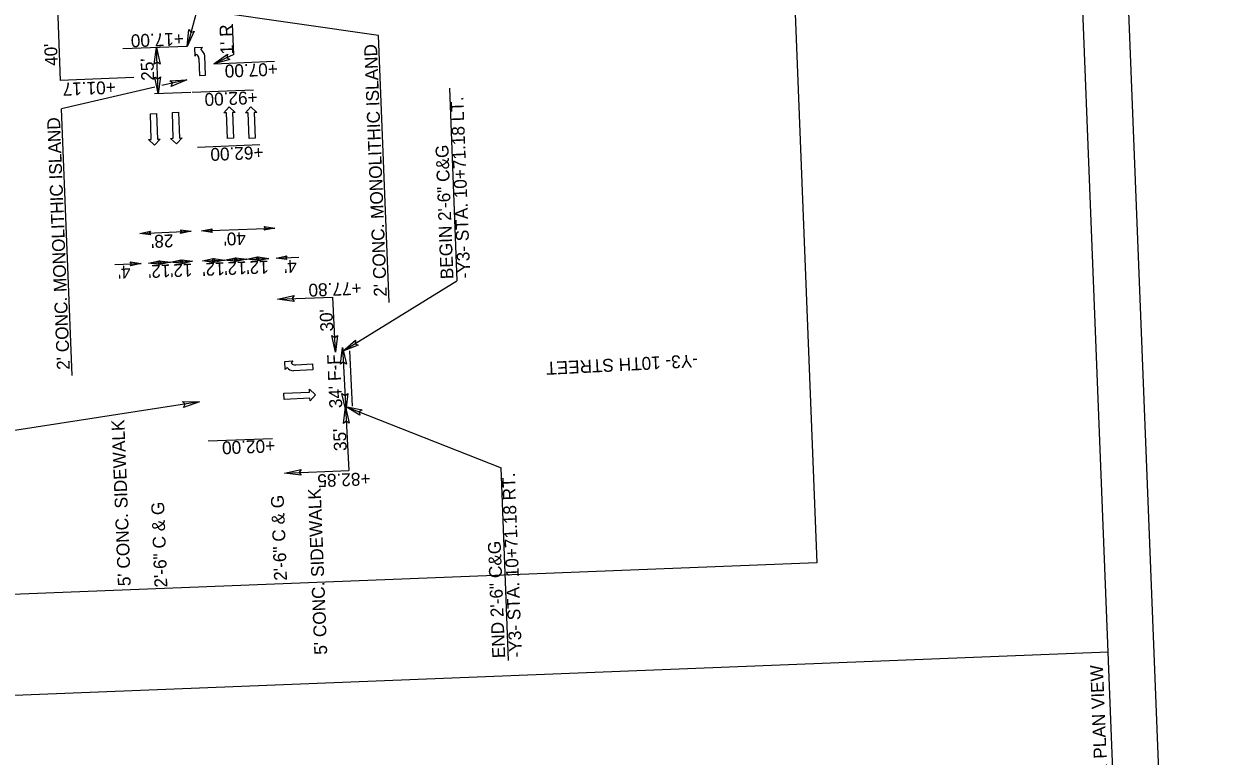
# Model space of a CAD drawing. Extents: x 1627847 to 1629013, y 761524 to 763498.
# Drawn here: x 1628362 to 1629013, y 762434 to 762832 of the extents above; entities that cross this region are included whole.
import ezdxf

# ---------------------------------------------------------------- set-up
doc = ezdxf.new("R2010")
doc.units = 0
for name, color, linetype in [('Default', 7, 'Continuous'), ('Prop Dimension', 7, 'Continuous'), ('Prop Dimension Text', 7, 'Continuous'), ('Prop DSN Text', 7, 'Continuous'), ('Prop Lane Arrow CELL', 7, 'Continuous'), ('Prop Terminator CELL', 7, 'Continuous'), ('Sheet Clip Boundary CELL', 7, 'Continuous'), ('Sheet Plan And Profile CELL', 7, 'Continuous'), ('Sheet Plot Border Outside CELL', 7, 'Continuous')]:
    doc.layers.add(name, color=color, linetype=linetype)

msp = doc.modelspace()

# ---------------------------------------------------------------- linework, layer by layer
at = {"layer": 'Prop Dimension'}
for p, q in [((1628380.25, 762841.46), (1628381.83, 762801.49)), ((1628455.98, 762838.88), (1628450.91, 762820.05)), ((1628555.02, 762825.91), (1628465.18, 762838.91)), ((1628476.2, 762815.65), (1628475.55, 762832.13)), ((1628560.75, 762680.76), (1628555.02, 762825.91)), ((1628450.91, 762820.05), (1628415.93, 762818.67)), ((1628435.17, 762794.41), (1628434.18, 762819.39)), ((1628476.2, 762815.65), (1628465.29, 762810.61)), ((1628465.29, 762810.61), (1628498.35, 762811.92)), ((1628421.8, 762803.07), (1628381.83, 762801.49)), ((1628450.62, 762801.91), (1628437, 762798.75)), ((1628433.2, 762797.87), (1628382.56, 762786.1)), ((1628433.18, 762794.34), (1628452.89, 762795.11)), ((1628453.53, 762795.14), (1628486.96, 762796.46)), ((1628593.53, 762797.3), (1628597.66, 762692.41)), ((1628388.28, 762640.95), (1628382.56, 762786.1)), ((1628456.54, 762765.23), (1628490.44, 762766.57)), ((1628425.15, 762718.31), (1628453.12, 762719.42)), ((1628458.62, 762719.63), (1628498.59, 762721.21)), ((1628441.78, 762702.6), (1628453.77, 762703.08)), ((1628459.26, 762703.29), (1628471.25, 762703.77)), ((1628471.25, 762703.77), (1628483.25, 762704.24)), ((1628483.25, 762704.24), (1628495.24, 762704.71)), ((1628499.23, 762704.87), (1628511.64, 762705.36)), ((1628411.49, 762701.41), (1628425.79, 762701.97)), ((1628429.79, 762702.13), (1628441.78, 762702.6)), ((1628535.51, 762654.11), (1628597.66, 762692.41)), ((1628500.08, 762682.48), (1628530.06, 762683.66)), ((1628531.58, 762653.7), (1628530.06, 762683.66)), ((1628535.41, 762656.11), (1628537.14, 762622.15)), ((1628457.54, 762626.57), (1628285.96, 762600.1)), ((1628537.01, 762623.94), (1628538.78, 762589.19)), ((1628537.04, 762624.15), (1628621.61, 762590.77)), ((1628462.38, 762605.34), (1628497.35, 762606.72)), ((1628503.85, 762587.81), (1628538.78, 762589.19)), ((1628625.75, 762485.94), (1628621.61, 762590.77)), ((1627902.73, 762449.14), (1628951.92, 762490.52))]:
    msp.add_line(p, q, dxfattribs=at)
at = {"layer": 'Prop Dimension Text'}
msp.add_line((1628540.86, 762624.34), (1628539.33, 762654.3), dxfattribs=at)
at = {"layer": 'Prop Lane Arrow CELL'}
for p, q in [((1628459.28, 762819.36), (1628454.89, 762819.25)), ((1628454.89, 762819.25), (1628455, 762814.75)), ((1628455, 762814.75), (1628456.01, 762815.84)), ((1628458.27, 762818.27), (1628459.28, 762819.36)), ((1628460.87, 762804.36), (1628460.49, 762814.9)), ((1628457.25, 762813.38), (1628457.58, 762804.24)), ((1628457.58, 762804.24), (1628460.87, 762804.36)), ((1628430.85, 762783.39), (1628434.15, 762783.51)), ((1628431.35, 762769.4), (1628430.85, 762783.39)), ((1628434.15, 762783.51), (1628434.65, 762769.52)), ((1628442.82, 762784.05), (1628446.12, 762784.17)), ((1628443.33, 762770.06), (1628442.82, 762784.05)), ((1628446.12, 762784.17), (1628446.62, 762770.18)), ((1628470.74, 762783.88), (1628473.72, 762787.14)), ((1628472.24, 762783.94), (1628470.74, 762783.88)), ((1628472.74, 762769.94), (1628472.24, 762783.94)), ((1628473.72, 762787.14), (1628477.03, 762784.11)), ((1628477.03, 762784.11), (1628475.53, 762784.05)), ((1628475.53, 762784.05), (1628476.04, 762770.06)), ((1628482.54, 762783.87), (1628485.53, 762787.13)), ((1628484.04, 762783.93), (1628482.54, 762783.87)), ((1628484.54, 762769.94), (1628484.04, 762783.93)), ((1628485.53, 762787.13), (1628488.84, 762784.1)), ((1628488.84, 762784.1), (1628487.34, 762784.05)), ((1628487.34, 762784.05), (1628487.84, 762770.06)), ((1628429.85, 762769.34), (1628431.35, 762769.4)), ((1628433.16, 762766.31), (1628429.85, 762769.34)), ((1628436.15, 762769.57), (1628433.16, 762766.31)), ((1628434.65, 762769.52), (1628436.15, 762769.57)), ((1628441.83, 762770.01), (1628443.33, 762770.06)), ((1628445.14, 762766.97), (1628441.83, 762770.01)), ((1628448.12, 762770.23), (1628445.14, 762766.97)), ((1628446.62, 762770.18), (1628448.12, 762770.23)), ((1628476.04, 762770.06), (1628472.74, 762769.94)), ((1628487.84, 762770.06), (1628484.54, 762769.94)), ((1628503.92, 762648.65), (1628508.41, 762648.94)), ((1628504.2, 762644.26), (1628503.92, 762648.65)), ((1628505.2, 762645.36), (1628504.2, 762644.26)), ((1628508.41, 762648.94), (1628507.42, 762647.83)), ((1628509.98, 762646.82), (1628519.11, 762647.31)), ((1628519.11, 762647.31), (1628519.29, 762644.01)), ((1628519.29, 762644.01), (1628508.75, 762643.45)), ((1628503.51, 762631.27), (1628517.5, 762631.93)), ((1628503.67, 762627.97), (1628503.51, 762631.27)), ((1628517.5, 762631.93), (1628517.43, 762633.43)), ((1628517.43, 762633.43), (1628520.72, 762630.48)), ((1628517.65, 762628.63), (1628503.67, 762627.97)), ((1628517.72, 762627.13), (1628517.65, 762628.63)), ((1628520.72, 762630.48), (1628517.72, 762627.13))]:
    msp.add_line(p, q, dxfattribs=at)
for centre, radius, start, end in [((1628453.99, 762813.28), 3.28, 2.05859, 51.71676), ((1628455.35, 762813.92), 5.25, 10.73466, 56.04636), ((1628509.27, 762648.66), 5.25, 219.07341, 264.3851), ((1628509.79, 762650.07), 3.28, 223.403, 273.06118)]:
    msp.add_arc(centre, radius, start, end, dxfattribs=at)
at = {"layer": 'Prop Terminator CELL'}
for points in [[(1628454.75, 762828.34), (1628450.91, 762820.05), (1628451.72, 762829.21), (1628452.96, 762827.68)], [(1628432.99, 762810.34), (1628434.18, 762819.39), (1628436.14, 762810.41), (1628434.5, 762811.5)], [(1628474.11, 762812.98), (1628465.29, 762810.61), (1628472.83, 762815.86), (1628472.46, 762813.93)], [(1628436.36, 762803.47), (1628435.17, 762794.41), (1628433.21, 762803.39), (1628434.86, 762802.31)], [(1628441.5, 762801.39), (1628450.62, 762801.91), (1628442.17, 762798.31), (1628442.93, 762800.13)], [(1628431.02, 762717.48), (1628425.15, 762718.31), (1628430.99, 762719.53), (1628430.28, 762718.47)], [(1628447.25, 762720.25), (1628453.12, 762719.42), (1628447.28, 762718.2), (1628447.99, 762719.26)], [(1628464.5, 762718.8), (1628458.62, 762719.63), (1628464.47, 762720.85), (1628463.75, 762719.79)], [(1628492.71, 762722.04), (1628498.59, 762721.21), (1628492.74, 762719.99), (1628493.46, 762721.06)], [(1628435.67, 762701.35), (1628429.79, 762702.13), (1628435.62, 762703.4), (1628434.92, 762702.33)], [(1628435.89, 762703.38), (1628441.78, 762702.6), (1628435.94, 762701.33), (1628436.65, 762702.4)], [(1628447.66, 762701.83), (1628441.78, 762702.6), (1628447.61, 762703.87), (1628446.91, 762702.81)], [(1628447.88, 762703.85), (1628453.77, 762703.08), (1628447.93, 762701.8), (1628448.64, 762702.87)], [(1628465.15, 762702.52), (1628459.26, 762703.29), (1628465.1, 762704.56), (1628464.4, 762703.49)], [(1628465.37, 762704.54), (1628471.25, 762703.77), (1628465.42, 762702.49), (1628466.12, 762703.56)], [(1628477.14, 762702.99), (1628471.25, 762703.77), (1628477.09, 762705.04), (1628476.39, 762703.97)], [(1628477.36, 762705.01), (1628483.25, 762704.24), (1628477.41, 762702.97), (1628478.11, 762704.04)], [(1628489.13, 762703.46), (1628483.25, 762704.24), (1628489.08, 762705.51), (1628488.38, 762704.44)], [(1628489.35, 762705.49), (1628495.24, 762704.71), (1628489.4, 762703.44), (1628490.11, 762704.51)], [(1628505.12, 762704.09), (1628499.23, 762704.87), (1628505.07, 762706.14), (1628504.36, 762705.07)], [(1628419.9, 762702.75), (1628425.79, 762701.97), (1628419.95, 762700.7), (1628420.66, 762701.77)], [(1628509.13, 762681.28), (1628500.08, 762682.48), (1628509.06, 762684.43), (1628507.97, 762682.79)], [(1628532.67, 762662.77), (1628531.58, 762653.7), (1628529.53, 762662.66), (1628531.18, 762661.59)], [(1628543.98, 762657.51), (1628535.51, 762654.11), (1628542.38, 762660.22), (1628542.24, 762658.25)], [(1628534.32, 762647.04), (1628535.41, 762656.11), (1628537.47, 762647.15), (1628535.81, 762648.22)], [(1628448.4, 762626.73), (1628457.54, 762626.57), (1628448.84, 762623.61), (1628449.73, 762625.37)], [(1628538.23, 762631.22), (1628537.14, 762622.15), (1628535.08, 762631.11), (1628536.74, 762630.04)], [(1628535.92, 762614.87), (1628537.01, 762623.94), (1628539.07, 762614.98), (1628537.41, 762616.05)], [(1628544.84, 762619.4), (1628537.04, 762624.15), (1628546.04, 762622.31), (1628544.39, 762621.25)], [(1628512.9, 762586.62), (1628503.85, 762587.81), (1628512.83, 762589.77), (1628511.74, 762588.13)]]:
    msp.add_lwpolyline(points, close=True, dxfattribs=at)
at = {"layer": 'Sheet Clip Boundary CELL'}
msp.add_lwpolyline([(1628097.28, 762511.58), (1628072.8, 763132.43), (1628198.63, 763137.39), (1628215.93, 763082.79), (1628256.43, 763089.13), (1628269.19, 763140.18), (1628768.96, 763159.88), (1628793.44, 762539.03)], close=True, dxfattribs=at)
at = {"layer": 'Sheet Plan And Profile CELL'}
msp.add_lwpolyline([(1627873.18, 763198.56), (1627932.28, 761699.73), (1628981.47, 761741.1), (1628922.36, 763239.94)], close=True, dxfattribs=at)
at = {"layer": 'Sheet Plot Border Outside CELL'}
msp.add_lwpolyline([(1629013.34, 761567.22), (1628946.36, 763265.9), (1627847.21, 763222.56), (1627914.2, 761523.88)], close=True, dxfattribs=at)

# ---------------------------------------------------------------- texts
at = {"layer": 'Default'}
msp.add_text('SEE SHEET 4 FOR PLAN VIEW', height=7, rotation=92.25819, dxfattribs=at).set_placement((1628954.47, 762347.3))
at = {"layer": 'Prop Dimension'}
for s, p in [('+17.00', (1628448.94, 762827.66)), ('+07.00', (1628500.05, 762811.18)), ('+92.00', (1628489.06, 762795.73)), ('+62.00', (1628492.24, 762765.83)), ('+02.00', (1628498.58, 762606.17))]:
    msp.add_text(s, height=7, rotation=182.25819, dxfattribs=at).set_placement(p)
at = {"layer": 'Prop Dimension Text'}
for s, rotation, p in [("1' R", 92.25819, (1628476.07, 762815.83)), ("40'", 93.07855, (1628380.64, 762809.62)), ("25'", 92.25819, (1628432.98, 762801.48)), ('+01.17', 182.25819, (1628411.87, 762801.28)), ('-Y3- STA. 10+71.18 LT.', 92.25819, (1628604.97, 762693.87)), ('BEGIN 2\'-6" C&G', 92.25819, (1628595.8, 762693.51)), ("28'", 182.25819, (1628443.25, 762717.8)), ("40'", 182.25819, (1628482.69, 762719.08)), ("12'", 182.25819, (1628483.12, 762703.07)), ("12'", 182.25819, (1628495.11, 762703.54)), ("4'", 182.25819, (1628510.42, 762703.96)), ("4'", 182.25819, (1628419.96, 762700.88)), ("12'", 182.25819, (1628441.65, 762701.43)), ("12'", 182.25819, (1628453.64, 762701.9)), ("12'", 182.25819, (1628471.18, 762702.6)), ('+77.80', 182.25819, (1628545.6, 762691.94)), ("30'", 92.42255, (1628530.4, 762665.02)), ("34' F-F", 92.56548, (1628535.28, 762623.31)), ("35'", 92.56548, (1628537.77, 762599.99)), ('+82.85', 182.25819, (1628550.45, 762588.25)), ('-Y3- STA. 10+71.18 RT.', 92.25819, (1628633.08, 762487.61)), ('END 2\'-6" C&G', 92.25819, (1628623.92, 762487.25))]:
    msp.add_text(s, height=7, rotation=rotation, dxfattribs=at).set_placement(p)
at = {"layer": 'Prop DSN Text'}
for s, rotation, p in [("2' CONC. MONOLITHIC ISLAND", 92.25819, (1628559.52, 762683.98)), ("2' CONC. MONOLITHIC ISLAND", 92.25819, (1628387.06, 762644.17)), ('-Y3- 10TH STREET', 182.9208, (1628728.58, 762652.49)), ("5' CONC. SIDEWALK", 92.25819, (1628420.23, 762526.42)), ("5' CONC. SIDEWALK", 92.25819, (1628527.08, 762489.13)), ('2\'-6" C & G', 92.25819, (1628505.2, 762529.41)), ('2\'-6" C & G', 92.25819, (1628440.11, 762525.7))]:
    msp.add_text(s, height=7, rotation=rotation, dxfattribs=at).set_placement(p)

doc.saveas('drawing.dxf')
